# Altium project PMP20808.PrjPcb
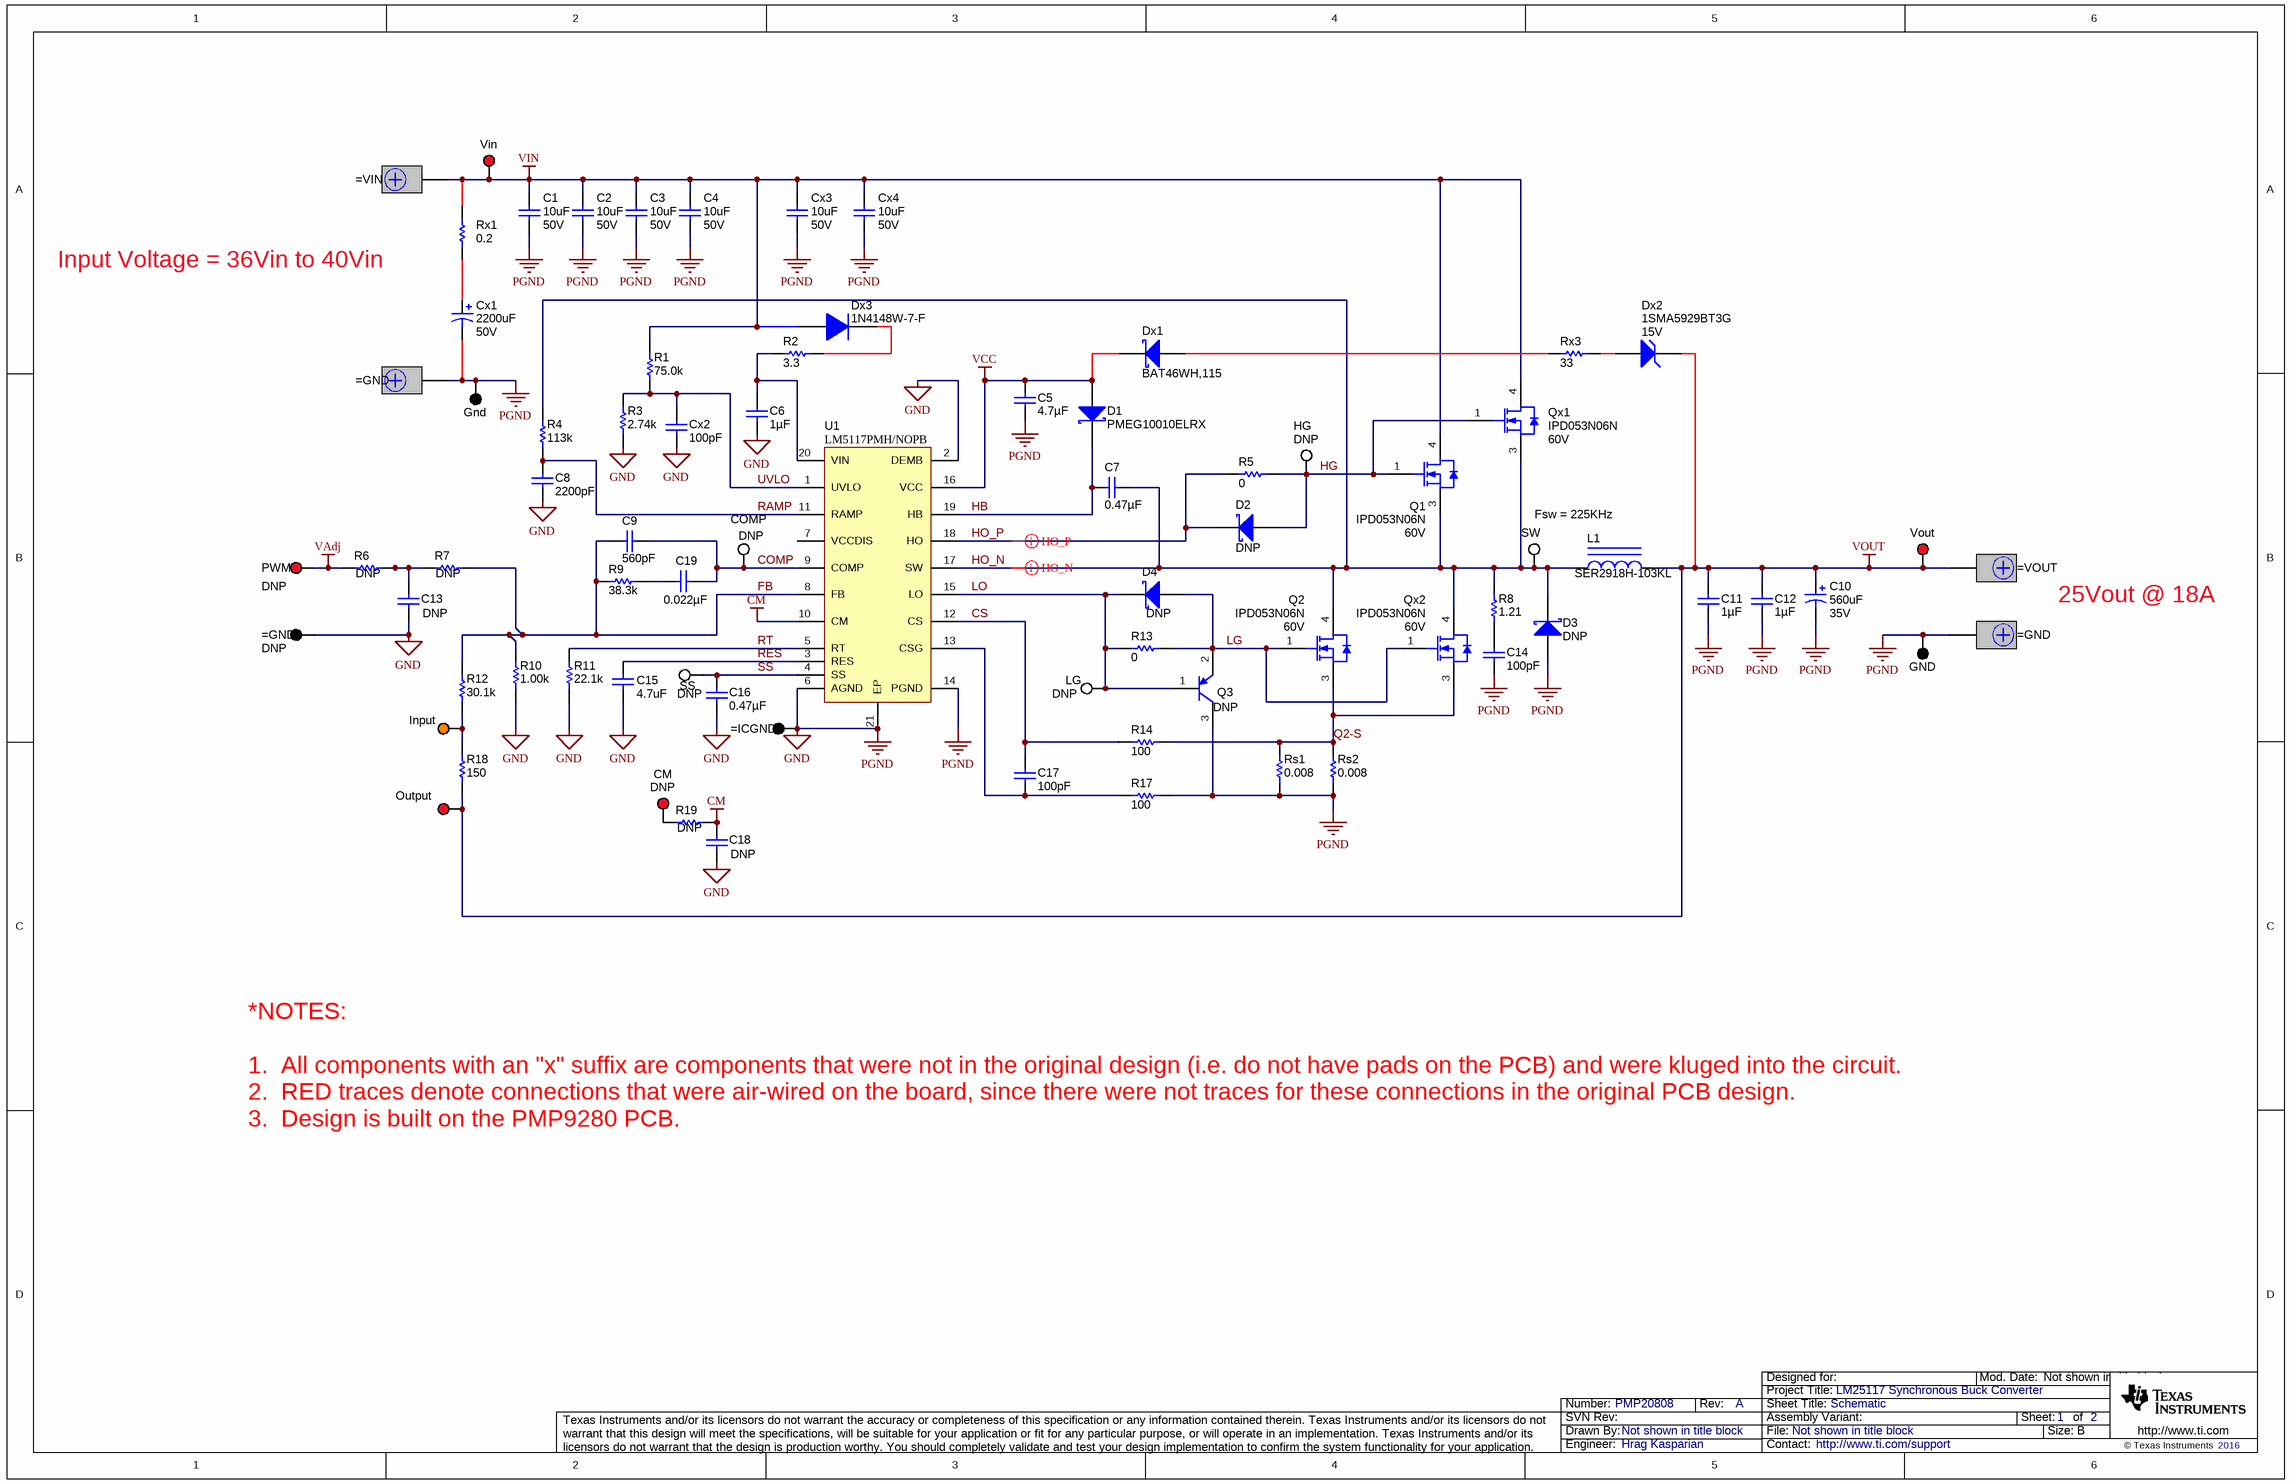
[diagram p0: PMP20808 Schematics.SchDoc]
CopyrightYear: 2016; PCB_Rev: A; PRJ_Engineer: Hrag Kasparian; PRJ_Number: PMP20808; PRJ_Title: LM25117 Synchronous Buck Converter; SCH_Rev: A; TechSupport: http://www.ti.com/support; TID: PMP20808
2 sheets, 91 parts. Net scope: global (net labels, ports and power ports of the same name join across sheets).
Board file: PMP9280 Rev 1.PcbDoc
Sheets:
  PMP20808 Schematics.SchDoc
  PMP20808_EVM_Hardware.SchDoc

## Sheet PMP20808 Schematics.SchDoc: Schematic
size 431 x 279 mm; Date: Not shown in title block; ApprovedBy: Not shown in title block; CheckedBy: Not shown in title block; Author: Not shown in title block; CompanyName: Not shown in title block; DrawnBy: Not shown in title block; Engineer: Not shown in title block; Organization: Not shown in title block; Address1: Not shown in title block; Address2: Not shown in title block; Address3: Not shown in title block; Address4: Not shown in title block; DocumentNumber: 1; Revision: Use project parameter SCH_Rev; SheetNumber: 1; SheetTotal: 2; PageSetup: Record=PageOptions¦CenterHorizontal=True¦CenterVertical=True¦PrintScale=0.62¦XCorrection=1.00¦YCorrection=1.00¦PrintKind=0¦BorderSize=5000000¦LeftOffset=0¦BottomOffset=0¦Orientation=2¦PaperLength=1000¦PaperWidth=1000¦Scale=100¦PaperSource=15¦PrintQuality=600¦MediaType=1¦DitherType=10¦PaperKind=Letter¦PrintScaleMode=1

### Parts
C1  value 10uF  Value1: 50V  [1210]  (hidden comment: GRM32ER71H106MA12L)
C2  value 10uF  Value1: 50V  [1210]  (hidden comment: GRM32ER71H106MA12L)
C3  value 10uF  Value1: 50V  [1210]  (hidden comment: GRM32ER71H106MA12L)
C4  value 10uF  Value1: 50V  [1210]  (hidden comment: GRM32ER71H106MA12L)
C5  ValueDisplayed: 4.7µF  [0805_HV]  (hidden comment: GRM21BR71E475KA73L)
C6  ValueDisplayed: 1µF  [1206]  (hidden comment: GRM31CR72A105KA01L)
C7  ValueDisplayed: 0.47µF  [0603]  (hidden comment: C1608X7R1H474K080AC)
C8  ValueDisplayed: 2200pF  [0603]  (hidden comment: GRM1885C1H222JA01D)
C9  ValueDisplayed: 560pF  [0603]  (hidden comment: GRM1885C1E561JA01D)
C10  value 560uF  Value1: 35V  [TBD]  (hidden comment: UCZ1V561MNQ1MS)
C11  ValueDisplayed: 1µF  [0805_HV]  (hidden comment: GRM21BR71H105KA12L)
C12  ValueDisplayed: 1µF  [0805_HV]  (hidden comment: GRM21BR71H105KA12L)
C13  DNP  [0603L]
C14  ValueDisplayed: 100pF  [0805_HV]  (hidden comment: GRM2165C2A101JA01D)
C15  value 4.7uF  [0805]  (hidden comment: C0805C475K4RACTU)
C16  ValueDisplayed: 0.47µF  [0603]  (hidden comment: GRM188R71C474KA88D)
C17  ValueDisplayed: 100pF  [0603L]  (hidden comment: GRM1885C1H101JA01D)
C18  DNP  [0603L]
C19  ValueDisplayed: 0.022µF  [0603]  (hidden comment: C0603C223K5RACTU)
CM  DNP  [Keystone5000]
COMP  DNP  [Keystone5002]
Cx1  value 2200uF  Value1: 50V  [TBD]  (hidden comment: 50YXJ2200M16X35.5)
Cx2  ValueDisplayed: 100pF  [0603]  (hidden comment: 06035A101FAT2A)
Cx3  value 10uF  Value1: 50V  [1210]  (hidden comment: GRM32ER71H106MA12L)
Cx4  value 10uF  Value1: 50V  [1210]  (hidden comment: GRM32ER71H106MA12L)
D1  PMEG10010ELRX  [SOD-123W]
D2  DNP  [sod-323]
D3  DNP  [powerDI123]
D4  DNP  [sod-323]
Dx1  BAT46WH,115  [SOD-123F]
Dx2  1SMA5929BT3G  value 15V  [SMA]
Dx3  1N4148W-7-F  [SOD-123]
Gnd  5011  [Keystone5011]  (value not drawn)
Gnd2  GND  [Keystone5011]  (value not drawn)
Gnd3  (no value)  [Keystone5011]
Gnd4  (no value)  [Keystone5011]
HG  DNP  [Keystone5002]
Input  (no value)  [Keystone5003]
J1  Vin 6V-32V  [CB35-36-CY]  (value not drawn)
J2  (no value)  [CB35-36-CY]
J3  (no value)  [CB35-36-CY]
J4  (no value)  [CB35-36-CY]
L1  SER2918H-103KL  [SER2918]
LG  DNP  [Keystone5002]
Output  (no value)  [Keystone5000]
PWM  DNP  [Keystone5000]
Q1  IPD053N06N  value 60V  [DPAK]
Q2  IPD053N06N  value 60V  [DPAK]
Q3  DNP  [SOT-23]
Qx1  IPD053N06N  value 60V  [DPAK]
Qx2  IPD053N06N  value 60V  [DPAK]
R1  ValueDisplayed: 75.0k  [0603]  (hidden comment: CRCW060375K0FKEA)
R2  ValueDisplayed: 3.3  [0603]  (hidden comment: CRCW06033R30JNEA)
R3  ValueDisplayed: 2.74k  [0603]  (hidden comment: CRCW06032K74FKEA)
R4  ValueDisplayed: 113k  [0603]  (hidden comment: CRCW0603113KFKEA)
R5  value 0  [0603L]  (hidden comment: CRCW06030000Z0EA)
R6  DNP  [0603L]
R7  DNP  [0603L]
R8  value 1.21  [0805_HV]  (hidden comment: CRCW08051R21FKEA)
R9  ValueDisplayed: 38.3k  [0603]  (hidden comment: CRCW060338K3FKEA)
R10  ValueDisplayed: 1.00k  [0603]  (hidden comment: CRCW06031K00FKEA)
R11  ValueDisplayed: 22.1k  [0603]  (hidden comment: CRCW060322K1FKEA)
R12  ValueDisplayed: 30.1k  [0603]  (hidden comment: CRCW060330K1FKEA)
R13  value 0  [0603L]  (hidden comment: CRCW06030000Z0EA)
R14  value 100  [0603L]  (hidden comment: CRCW0603100RFKEA)
R17  value 100  [0603L]  (hidden comment: CRCW0603100RFKEA)
R18  ValueDisplayed: 150  [0603]  (hidden comment: CRCW0603150RFKEA)
R19  DNP  [0603L]
Rs1  value 0.008  [2512M]  (hidden comment: ERJ-M1WSF8M0U)
Rs2  value 0.008  [2512M]  (hidden comment: ERJ-M1WSF8M0U)
Rx1  value 0.2  [TBD]  (hidden comment: NKN2WSJT-73-0R2)
Rx3  ValueDisplayed: 33  [1206]  (hidden comment: CRCW120633R0JNEA)
SS  DNP  [Keystone5002]
SW  5002  [Keystone5002]  (value not drawn)
U1  LM5117PMH/NOPB  [MXA20A_N]
Vin  5000  [Keystone5000]  (value not drawn)
Vout  Vout 2.2V to 13V@ 15A  [Keystone5000]  (value not drawn)

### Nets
CM: C18.1 R19.1 U1.10(CM)
GND: C1.2 C2.2 C3.2 C4.2 C5.2 C6.2 C8.2 C10.2(-) C11.2 C12.2 C13.2 C14.2 C15.2 C16.2 C18.2 Cx1.2(-) Cx2.2 Cx3.2 Cx4.2 D3.2(A) Gnd.1 Gnd2.1 Gnd3.1 Gnd4.1 J2.1 J4.1 Q3.3(C) R3.1 R10.1 R11.1 R17.2 Rs1.1 Rs2.1 U1.2(DEMB) U1.6(AGND) U1.14(PGND) U1.21(EP)  [also labelled PGND]
VAdj: PWM.1 R6.1
VCC: C5.1 D1.2(A) Dx1.1(K) U1.16(VCC)
VIN: C1.1 C2.1 C3.1 C4.1 Cx3.1 Cx4.1 Dx3.2(A) J1.1 Q1.4(D) Qx1.4(D) R1.2 Rx1.2 Vin.1
VOUT: C10.1(+) C11.1 C12.1 Dx2.1(K) J3.1 L1.2 Output.1 R18.1 Vout.1
COMP: C9.1 C19.1 COMP.1 U1.9(COMP)
CS: C17.1 R14.1 U1.12(CS)
FB: C9.2 R7.1 R9.1 R10.2 R12.2 U1.8(FB)
HB: C7.1 D1.1(K) U1.19(HB)
HG: D2.2(A) HG.1 Q1.1(G) Qx1.1(G) R5.2
HO_N: C7.2 D3.1(K) L1.1 Q1.3(S) Q2.4(D) Qx1.3(S) Qx2.4(D) R4.2 R8.2 SW.1 U1.17(SW)
HO_P: D2.1(K) R5.1 U1.18(HO)
LG: D4.2(A) Q2.1(G) Q3.2(E) Qx2.1(G) R13.2
LO: D4.1(K) LG.1 Q3.1(B) R13.1 U1.15(LO)
Q2-S: Q2.3(S) Qx2.3(S) R14.2 Rs1.2 Rs2.2
RAMP: C8.1 R4.1 U1.11(RAMP)
RES: C15.1 U1.3(RES)
RT: R11.2 U1.5(RT)
SS: C16.1 SS.1 U1.4(SS)
UVLO: Cx2.1 R1.1 R3.2 U1.1(UVLO)
NetC6_1: C6.1 R2.1 U1.20(VIN)
NetC13_1: C13.1 R6.2 R7.2
NetC14_1: C14.1 R8.1
NetC17_2: C17.2 R17.1 U1.13(CSG)
NetC19_2: C19.2 R9.2
NetCM_1: CM.1 R19.2
NetCx1_1: Cx1.1(+) Rx1.1
NetDx1_2: Dx1.2(A) Rx3.1
NetDx2_2: Dx2.2(A) Rx3.2
NetDx3_1: Dx3.1(K) R2.2
NetInput_1: Input.1 R12.1 R18.2

Not connected (* = marked no-connect by the designer): U1 7(VCCDIS)

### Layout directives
differential pair: HO_N, HO_P

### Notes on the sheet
- Input Voltage = 36Vin to 40Vin
- Fsw = 225KHz
- 25Vout @ 18A
- *NOTES:
  1.  All components with an "x" suffix are components that were not in the original design (i.e. do not have pads on the PCB) and were kluged into the circuit.
  2.  RED traces denote connections that were air-wired on the board, since there were not traces for these connections in the original PCB design.
  3.  Design is built on the PMP9280 PCB.

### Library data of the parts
C1-C4 Cx3 Cx4 = Capacitor: CAP, CERM, 10uF, 50V, X7R, 20%, 1210; Manufacturer: Murata; Polarized: N; U/M: EA
C5 = GRM21BR71E475KA73L: CAP, CERM, 4.7 µF, 25 V, +/- 10%, X7R, 0805; Manufacturer: MuRata; Polarized: N; CompType: Capacitor; Value: 4.7uF; U/M: EA; Cap_F: 0.0000047; Tolerance_%: 10; Value1: Unknown; VDC_V: 25; Value2: 25V; TaMin_C: -55; TaMax_C: 125; Cap_Case: 0805; SizeArea_mm2: 2.5; SizeAreaWB_mm2: 6.75; SizeX_mm: 2; SizeY_mm: 1.25; SizeZ_mm: 1.45; AEC Category: Q200
C6 = GRM31CR72A105KA01L: CAP, CERM, 1uF, 100V, +/-10%, X7R, 1206; Manufacturer: MuRata; Polarized: N; CompType: Capacitor; U/M: EA; Cap_F: 0.000001; Tolerance_%: 10; Value1: Unknown; VDC_V: 100; TaMin_C: -55; TaMax_C: 125; Cap_Case: 2220
C7 = C1608X7R1H474K080AC: CAP, CERM, 0.47 µF, 50 V, +/- 10%, X7R, 0603; Manufacturer: TDK; Polarized: N; CompType: Capacitor; Value: 0.47uF; U/M: EA; Cap_F: 0.00000047; Tolerance_%: 10; ESR_ohm: 0.010974; Value1: 0.010974 ohm; VDC_V: 50; Value2: 50V; IRMS_A: 1.57483; TaMin_C: -55; TaMax_C: 125; SizeArea_mm2: 1.28; SizeAreaWB_mm2: 4.68; SizeX_mm: 1.6; SizeY_mm: 0.8; SizeZ_mm: 1; AEC Category: Q200
C8 = GRM1885C1H222JA01D: CAP, CERM, 2200pF, 50V, +/-5%, C0G/NP0, 0603; Manufacturer: MuRata; Polarized: N; CompType: Capacitor; U/M: EA; Cap_F: 0.0000000022; Tolerance_%: 5; Value1: Unknown; VDC_V: 50; TaMin_C: -55; TaMax_C: 125
C9 = GRM1885C1E561JA01D: CAP, CERM, 560 pF, 25 V, +/- 5%, C0G/NP0, 0603; Manufacturer: MuRata; Polarized: N; CompType: Capacitor; Value: 560pF; U/M: EA; Cap_F: 0.00000000056; Tolerance_%: 5; Value1: Unknown; VDC_V: 25; Value2: 25V; TaMin_C: -55; TaMax_C: 125; SizeArea_mm2: 1.28; SizeAreaWB_mm2: 4.68; SizeX_mm: 1.6; SizeY_mm: 0.8; SizeZ_mm: 1; AEC Category: Q200
C10 = Capacitor_Polarized: CAP, Al Electrolytic, 560uF, 35V, +/-20%, 0.06 Ohm ESR, 1.7Arms, SMT; Manufacturer: Nichicon; Polarized: Y; U/M: EA
C11 C12 = GRM21BR71H105KA12L: CAP, CERM, 1 µF, 50 V, +/- 10%, X7R, 0805; Manufacturer: MuRata; Polarized: N; CompType: Capacitor; Value: 1uF; U/M: EA; Cap_F: 0.000001; Tolerance_%: 10; Value1: Unknown; VDC_V: 50; Value2: 50V; TaMin_C: -55; TaMax_C: 125; Cap_Case: 0805; SizeArea_mm2: 2.5; SizeAreaWB_mm2: 6.75; SizeX_mm: 2; SizeY_mm: 1.25; SizeZ_mm: 1.45; AEC Category: Q200
C13 = GRM188R60J106ME47D: CAP, CERM, 10uF, 6.3V, +/-20%, X5R, 0603; Manufacturer: MuRata; Polarized: N; CompType: Capacitor; ValueDisplayed: 10µF; U/M: EA; Cap_F: 0.00001; Tolerance_%: 20; ESR_Ohm: 0.009; Value1: 0.009 ohm; VDC_V: 6.3; IRMS_A: 2.74; TaMin_C: -55; TaMax_C: 125; Cap_Case: 0603
C14 = GRM2165C2A101JA01D: CAP, CERM, 100 pF, 100 V, +/- 5%, C0G/NP0, 0805; Manufacturer: MuRata; Cap_Case: 0805; Polarized: N; TaMax_C: 125; TaMin_C: -55; Tolerance_%: 5; VDC_V: 100; Cap_F: 0.0000000001; CompType: Capacitor; Value: 100pF; U/M: EA; Value1: Unknown; Value2: 100V; SizeArea_mm2: 2.5; SizeAreaWB_mm2: 6.75; SizeX_mm: 2; SizeY_mm: 1.25; SizeZ_mm: 1.45; AEC Category: Q200
C15 = Capacitor: CAP, CERM, 4.7uF, 16V, X7R, 10%, 0805; Manufacturer: Kemet; Polarized: N; U/M: EA
C16 = GRM188R71C474KA88D: CAP, CERM, 0.47 µF, 16 V, +/- 10%, X7R, 0603; Manufacturer: MuRata; Polarized: N; CompType: Capacitor; Value: 0.47uF; U/M: EA; Cap_F: 0.00000047; Tolerance_%: 10; Value1: Unknown; VDC_V: 16; Value2: 16V; TaMin_C: -55; TaMax_C: 125; SizeArea_mm2: 1.28; SizeAreaWB_mm2: 4.68; SizeX_mm: 1.6; SizeY_mm: 0.8; SizeZ_mm: 1; AEC Category: Q200
C17 = GRM1885C1H101JA01D: CAP, CERM, 100pF, 50V, +/-5%, C0G/NP0, 0603; Manufacturer: MuRata; Polarized: N; CompType: Capacitor; U/M: EA; Cap_F: 0.0000000001; Tolerance_%: 5; Value1: Unknown; VDC_V: 50; TaMin_C: -55; TaMax_C: 125; Cap_Case: 0603
C18 = GRM188R61H103KA01D: CAP, CERM, 0.01uF, 50V, +/-10%, X5R, 0603; Manufacturer: MuRata; Polarized: N; CompType: Capacitor; ValueDisplayed: 0.01µF; U/M: EA; Cap_F: 0.00000001; Tolerance_%: 10; Value1: Unknown; VDC_V: 50; TaMin_C: -55; TaMax_C: 85; Cap_Case: 0603
C19 = C0603C223K5RACTU: CAP, CERM, 0.022uF, 50V, +/-10%, X7R, 0603; Manufacturer: Kemet; Polarized: N; CompType: Capacitor; U/M: EA; Cap_F: 0.000000022; Tolerance_%: 10; Value1: Unknown; VDC_V: 50; TaMin_C: -55; TaMax_C: 125
CM Output PWM Vin Vout = 5000: Test Point, Miniature, Red, TH; Manufacturer: Keystone; CompType: Test Point Loop; U/M: EA
COMP HG LG SS SW = 5002: Test Point, Miniature, White, TH; Manufacturer: Keystone; CompType: Test Point Loop; U/M: EA
Cx1 = Capacitor_Polarized: CAP, Al Electrolytic, 2200uF, 50V, +/-20%, 0.019Ohm ESR, 3.15Arms, TH; Manufacturer: Rubycon; Polarized: Y; U/M: EA
Cx2 = 06035A101FAT2A: CAP, CERM, 100pF, 50V, +/-1%, C0G/NP0, 0603; Manufacturer: AVX; Polarized: N; CompType: Capacitor; U/M: EA; Cap_F: 0.0000000001; Tolerance_%: 1; Value1: Unknown; VDC_V: 50; TaMin_C: -55; TaMax_C: 125
D1 = PMEG10010ELRX: Diode, Schottky, 100 V, 1 A, AEC-Q101, SOD-123W; Manufacturer: NXP Semiconductor; Value: 100V; U/M: EA; Vf_V: 0.77; Value1: 1A; Value2: 0.77V; Io_A: 1; Vr_V: 100; TJmax_C: 175; SizeAreaWB_mm2: 12.15; SizeArea_mm2: 5.95; SizeX_mm: 3.5; SizeY_mm: 1.7; AEC Category: Q101; AEC Qualified: Y
D2 D4 = BAT42WS-7-F: Diode, Schottky, 30V, 0.2A, SOD-323; Manufacturer: Diodes Inc.; U/M: EA; Vf_V: 1; Value2: 1V; Io_A: 0.2; Vr_V: 30
D3 = Diode_Schottky: Diode, Schottky, 60V, 2A, PowerDI 123; Manufacturer: Diodes Inc.; PartNumber: DFLS260Q-7; U/M: EA
Dx1 = BAT46WH,115: Diode, Schottky, 100 V, 0.25 A, SOD-123F; Manufacturer: NXP Semiconductor; Value: 100V; U/M: EA; Vf_V: 0.85; Value1: 0.25A; Value2: 0.85V; Io_A: 0.25; Vr_V: 100; TJmax_C: 150; SizeAreaWB_mm2: 11.7; SizeArea_mm2: 5.6; SizeX_mm: 3.5; SizeY_mm: 1.6; SizeZ_mm: 1.1; AEC Category: Q101
Dx2 = 1SMA5929BT3G: Diode, Zener, 15 V, 500 mW, SMA; Manufacturer: ON Semiconductor; U/M: EA; SymbolCreator: a0412235; Power_W: 0.5; Vz_V: 15; Value1: 0.5W; SizeAreaWB_mm2: 37.3428; SizeArea_mm2: 16.3228; SizeX_mm: 5.59; SizeY_mm: 2.92; SizeZ_mm: 2.87; AEC Category: Q101
Dx3 = 1N4148W-7-F: Diode, Ultrafast, 100 V, 0.15 A, SOD-123; Manufacturer: Diodes Inc.; U/M: EA; Vf_V: 1.25; Value: 100V; Value1: 0.15A; Value2: 1.25V; Io_A: 0.15; Vr_V: 100; TJmax_C: 150; SizeAreaWB_mm2: 13.095; SizeArea_mm2: 6.545; SizeX_mm: 3.85; SizeY_mm: 1.7; SizeZ_mm: 1.35; AEC Category: Q101
Gnd Gnd2-Gnd4 = 5011: Test Point, TH, Multipurpose, Black; Manufacturer: Keystone; CompType: Test Point Loop; U/M: EA
Input = 5003: Test Point, Miniature, Orange, TH; Manufacturer: Keystone; CompType: Test Point Loop; ContactFinish: Silver
J1 = CB35-36-CY: Terminal 50A Lug; Manufacturer: Panduit; SymbolCreator: crossc; CompType: Screw Terminal; U/M: EA
J2 J4 = CB35-36-CY: Terminal 50A Lug; Manufacturer: Panduit; SymbolCreator: crossc; CompType: Screw Terminal; U/M: EA; Comment_1: GND
J3 = CB35-36-CY: Terminal 50A Lug; Manufacturer: Panduit; SymbolCreator: crossc; CompType: Screw Terminal; U/M: EA; Comment_1: VOUT
L1 = SER2918H-103KL: Inductor, Shielded E Core, Ferrite, 10uH, 28A, 0.0026 ohm, SMD; Manufacturer: Coilcraft; ValueDisplayed: 10µH; Ind_H: 10.0E-6; Imax_A: 28; Irms: 28A @ 40C rise; Isat: 32.1A @ 30% inductance drop; DCR_ohm: 0.0026
Q1 Q2 Qx1 Qx2 = MOSFET_N_D4G1S3: MOSFET, N-CH, 60V, 5.3mOhm Max. @ 10Vgs, DPAK; Manufacturer: Infineon; U/M: EA
Q3 = MMBT3906, Fairchild Semiconductor: Transistor, PNP, 40V, 0.2A, SOT-23; CompType: BJT; PNP: 1; NPN: 0; Vceo_V: 40; Vcesat1_V: 0.25; Value: 0.25V; IcRated_A: 0.2; HfeMax: 300; TaMin_C: -55; TaMax_C: 150; U/M: EA
R1 = CRCW060375K0FKEA: RES, 75.0 k, 1%, 0.1 W, 0603; Manufacturer: Vishay-Dale; CompType: Resistor; Value: 75.0k; Res_ohm: 75000; Value_Code: 75k0; Tolerance_%: 1; Power_W: 0.1; Value2: 0.1W; VDC_V: 75; TempCo: 100 ppm/C; EIA_Code: E96; U/M: EA; SizeArea_mm2: 1.28; SizeX_mm: 1.6; SizeY_mm: 0.8; AEC Category: Q200
R2 = CRCW06033R30JNEA: RES, 3.3, 5%, 0.1 W, 0603; Manufacturer: Vishay-Dale; CompType: Resistor; Value: 3.3; Value_Code: 3R30; Tolerance_%: 5; Power_W: 0.1; Value2: 0.1W; VDC_V: 75; TempCo: 200 ppm/C; EIA_Code: E24; U/M: EA; SizeArea_mm2: 1.28; SizeX_mm: 1.6; SizeY_mm: 0.8; SizeZ_mm: 1; AEC Category: Q200
R3 = CRCW06032K74FKEA: RES, 2.74 k, 1%, 0.1 W, 0603; Manufacturer: Vishay-Dale; CompType: Resistor; Value: 2.74k; Res_ohm: 2740; Value_Code: 2k74; Tolerance_%: 1; Power_W: 0.1; Value2: 0.1W; VDC_V: 75; TempCo: 100 ppm/C; EIA_Code: E96; U/M: EA; SizeArea_mm2: 1.28; SizeX_mm: 1.6; SizeY_mm: 0.8; AEC Category: Q200
R4 = CRCW0603113KFKEA: RES, 113 k, 1%, 0.1 W, 0603; Manufacturer: Vishay-Dale; CompType: Resistor; Value: 113k; Res_ohm: 113000; Tolerance_%: 1; Power_W: 0.1; Value2: 0.1W; VDC_V: 75; TempCo: 100 ppm/C; EIA_Code: E96; U/M: EA; SizeArea_mm2: 1.28; SizeX_mm: 1.6; SizeY_mm: 0.8; AEC Category: Q200
R5 R13 = CRCW06030000Z0EA: RES, 0 ohm, 5%, 0.1W, 0603; Manufacturer: Vishay-Dale; CompType: Resistor; Value_Code: 0000; Tolerance_%: 5; Power_W: 0.1; VDC_V: 75; TempCo: 200 ppm/C; EIA_Code: E24; U/M: EA
R6 R7 = CRCW06032K00FKEA: RES, 2.00k ohm, 1%, 0.1W, 0603; Manufacturer: Vishay-Dale; CompType: Resistor; Res_ohm: 2000; Value_Code: 2k00; Tolerance_%: 1; Power_W: 0.1; VDC_V: 75; TempCo: 100 ppm/C; EIA_Code: E96; U/M: EA
R8 = CRCW08051R21FKEA: RES, 1.21 ohm, 1%, 0.125W, 0805; Manufacturer: Vishay-Dale; CompType: Resistor; Tolerance_%: 1; VDC_V: 150; Power_W: 0.125; Value_Code: 1R21; EIA_Code: E96; U/M: EA; TempCo: 100 ppm/C
R9 = CRCW060338K3FKEA: RES, 38.3 k, 1%, 0.1 W, 0603; Manufacturer: Vishay-Dale; CompType: Resistor; Value: 38.3k; Res_ohm: 38300; Value_Code: 38k3; Tolerance_%: 1; Power_W: 0.1; Value2: 0.1W; VDC_V: 75; TempCo: 100 ppm/C; EIA_Code: E96; U/M: EA; SizeArea_mm2: 1.28; SizeX_mm: 1.6; SizeY_mm: 0.8; AEC Category: Q200
R10 = CRCW06031K00FKEA: RES, 1.00 k, 1%, 0.1 W, 0603; Manufacturer: Vishay-Dale; CompType: Resistor; Value: 1.00k; Res_ohm: 1000; Value_Code: 1k00; Tolerance_%: 1; Power_W: 0.1; Value2: 0.1W; VDC_V: 75; TempCo: 100 ppm/C; EIA_Code: E96; U/M: EA; SizeArea_mm2: 1.28; SizeX_mm: 1.6; SizeY_mm: 0.8; AEC Category: Q200
R11 = CRCW060322K1FKEA: RES, 22.1 k, 1%, 0.1 W, 0603; Manufacturer: Vishay-Dale; CompType: Resistor; Value: 22.1k; Res_ohm: 22100; Value_Code: 22k1; Tolerance_%: 1; Power_W: 0.1; Value2: 0.1W; VDC_V: 75; TempCo: 100 ppm/C; EIA_Code: E96; U/M: EA; SizeArea_mm2: 1.28; SizeX_mm: 1.6; SizeY_mm: 0.8; AEC Category: Q200
R12 = CRCW060330K1FKEA: RES, 30.1 k, 1%, 0.1 W, 0603; Manufacturer: Vishay-Dale; CompType: Resistor; Value: 30.1k; Res_ohm: 30100; Value_Code: 30k1; Tolerance_%: 1; Power_W: 0.1; Value2: 0.1W; VDC_V: 75; TempCo: 100 ppm/C; EIA_Code: E96; U/M: EA; SizeArea_mm2: 1.28; SizeX_mm: 1.6; SizeY_mm: 0.8; AEC Category: Q200
R14 R17 = CRCW0603100RFKEA: RES, 100 ohm, 1%, 0.1W, 0603; Manufacturer: Vishay-Dale; CompType: Resistor; Value_Code: 100R; Tolerance_%: 1; Power_W: 0.1; VDC_V: 75; TempCo: 100 ppm/C; EIA_Code: E96; U/M: EA
R18 = CRCW0603150RFKEA: RES, 150, 1%, 0.1 W, 0603; Manufacturer: Vishay-Dale; CompType: Resistor; Value: 150; Value_Code: 150R; Tolerance_%: 1; Power_W: 0.1; Value2: 0.1W; VDC_V: 75; TempCo: 100 ppm/C; EIA_Code: E96; U/M: EA; SizeArea_mm2: 1.28; SizeX_mm: 1.6; SizeY_mm: 0.8; AEC Category: Q200
R19 = CRCW06031K00JNEA: RES, 1.0k ohm, 5%, 0.1W, 0603; Manufacturer: Vishay-Dale; CompType: Resistor; Res_ohm: 1000; Value_Code: 1k00; Tolerance_%: 5; Power_W: 0.1; VDC_V: 75; TempCo: 200 ppm/C; EIA_Code: E24; U/M: EA
Rs1 Rs2 = ERJ-M1WSF8M0U: RES, 0.008 ohm, 1%, 1W, 2512; Manufacturer: Panasonic; CompType: Resistor; Value_Code: R008; Tolerance_%: 1; TempCo: 100 ppm/C; EIA_Code: E96; U/M: EA
Rx1 = Resistor: RES, 0.2 ohm, 5%, 2W, Axial TH; Manufacturer: Yageo; U/M: EA
Rx3 = CRCW120633R0JNEA: RES, 33, 5%, 0.25 W, 1206; Manufacturer: Vishay-Dale; CompType: Resistor; Value: 33; Value_Code: 33R0; Tolerance_%: 5; Power_W: 0.25; Value2: 0.25W; VDC_V: 200; TempCo: 200 ppm/C; EIA_Code: E24; U/M: EA; SizeArea_mm2: 5.12; SizeX_mm: 3.2; SizeY_mm: 1.6; SizeZ_mm: 1.35; AEC Category: Q200
U1 = LM5117PMH/NOPB: Wide Voltage Range Buck-Boost Controller, 20-pin TSSOP-EP, Pb-Free; Manufacturer: Texas Instruments; PackageTopMarking: NSUZXYTT*LM5118*MH; PowerWise: Y; CompType: Switcher; Isolated: No; Buck: Yes; Voltage - Supply: 5.5 V ~ 65 V; Duty Cycle: 95%; Frequency - Max: 530kHz; Number of Outputs: 1; PWM Type: Current Mode

## Sheet PMP20808_EVM_Hardware.SchDoc: Hardware
size 431 x 279 mm; Date: Not shown in title block; ApprovedBy: Not shown in title block; CheckedBy: Not shown in title block; Author: Not shown in title block; CompanyName: Not shown in title block; Engineer: Not shown in title block; Organization: Not shown in title block; Address1: Not shown in title block; Address2: Not shown in title block; Address3: Not shown in title block; Address4: Not shown in title block; DocumentNumber: 2; Revision: Use project parameter SCH_Rev; SheetNumber: 2; SheetTotal: 2; PageSetup: Record=PageOptions¦CenterHorizontal=True¦CenterVertical=True¦PrintScale=1.00¦XCorrection=1.00¦YCorrection=1.00¦PrintKind=0¦BorderSize=5000000¦LeftOffset=0¦BottomOffset=0¦Orientation=2¦PaperLength=1000¦PaperWidth=1000¦Scale=100¦PaperSource=15¦PrintQuality=600¦MediaType=1¦DitherType=10¦PaperKind=Letter¦PrintScaleMode=1
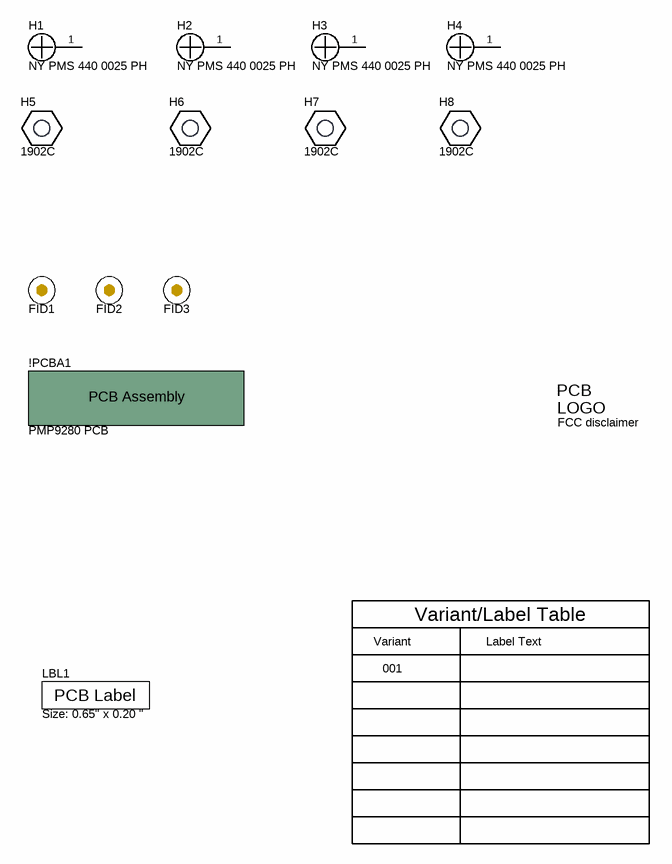
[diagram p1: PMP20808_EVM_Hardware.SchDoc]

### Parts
!PCBA1  PMP9280 PCB  (mechanical)
FID1  Fiducial  [Fiducial10-20]  (value not drawn)
FID2  Fiducial  [Fiducial10-20]  (value not drawn)
FID3  Fiducial  [Fiducial10-20]  (value not drawn)
H1  NY PMS 440 0025 PH  [NY PMS 440 0025 PH]
H2  NY PMS 440 0025 PH  [NY PMS 440 0025 PH]
H3  NY PMS 440 0025 PH  [NY PMS 440 0025 PH]
H4  NY PMS 440 0025 PH  [NY PMS 440 0025 PH]
H5  1902C  [Keystone_1902C]
H6  1902C  [Keystone_1902C]
H7  1902C  [Keystone_1902C]
H8  1902C  [Keystone_1902C]
LBL1  Size: 0.65" x 0.20 "  [Label_650x200]
Logo3  FCC disclaimer  [FCC_disclaimer]  (no BOM)

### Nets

Not connected (* = marked no-connect by the designer): H1 1; H2 1; H3 1; H4 1

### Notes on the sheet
- Variant
- Variant/Label Table
- Label Text
- 001

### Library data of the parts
!PCBA1 = PCBA: Manufacturer: Used in BOM report; SymbolCreator: a0412235; U/M: EA
FID1-FID3 = Fiducial: Fiducial mark.  There is nothing to buy or mount.; SymbolCreator: codlsc
H1-H4 = NY PMS 440 0025 PH: Machine Screw, Round, #4-40 x 1/4, Nylon, Philips panhead; Manufacturer: B&F Fastener Supply; CompType: Hardware; SymbolCreator: codlsc; U/M: EA
H5-H8 = 1902C: Standoff, Hex, 0.5"L #4-40 Nylon; Manufacturer: Keystone; CompType: Hardware
LBL1 = THT-14-423-10: Thermal Transfer Printable Labels, 0.650" W x 0.200" H - 10,000 per roll; Manufacturer: Brady; SymbolCreator: a0412235; CompType: Label
Logo3 = FCC_disclaimer: SymbolCreator: codlsc

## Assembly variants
001: not fitted C13 C18 CM COMP D2 D3 D4 FID1 FID2 FID3 HG LG PWM Q3 R6 R7 R19 SS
